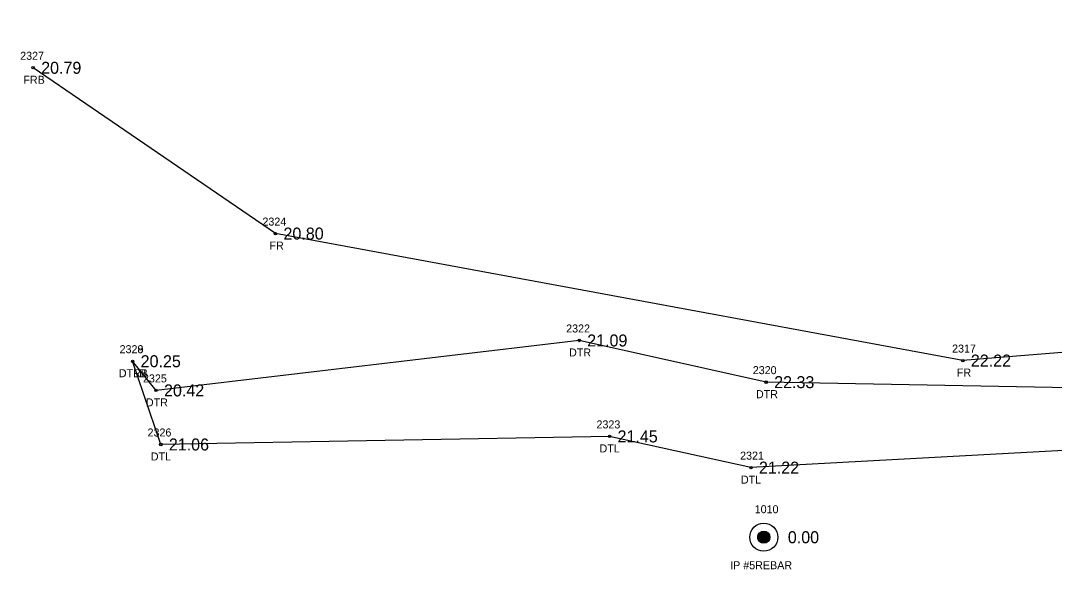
# Model space of a CAD drawing. Extents: x 2654414 to 2656963, y 761776 to 764965.
# Drawn here: x 2655219.9 to 2655349, y 762027.7 to 762096.2 of the extents above; entities that cross this region are included whole.
import ezdxf

# ---------------------------------------------------------------- set-up
doc = ezdxf.new("R2010")
doc.units = 0
for name, color, linetype in [('RD_EX_DV_Prop_txCode', 7, 'Continuous'), ('RD_EX_DV_PropPin', 7, 'Continuous'), ('RD_EX_Fence_Other', 7, 'Continuous'), ('RD_EX_Fence_Other_txCode', 7, 'Continuous'), ('RD_EX_H2O', 7, 'Continuous'), ('RD_EX_H2O_txCode', 7, 'Continuous'), ('RD_EX_TX_DV_Prop_ELEV', 7, 'Continuous'), ('RD_EX_TX_Fence_Other_ELEV', 7, 'Continuous'), ('RD_EX_TX_H2O_ELEV', 7, 'Continuous'), ('RD_SMD_Locator', 7, 'Continuous')]:
    doc.layers.add(name, color=color, linetype=linetype)

msp = doc.modelspace()

# ---------------------------------------------------------------- linework, layer by layer
at = {"layer": 'RD_EX_DV_PropPin'}
for p, q in [((2655312.11, 762031.2), (2655312.11, 762032.15)), ((2655312.15, 762031.16), (2655312.15, 762032.19)), ((2655312.18, 762031.12), (2655312.18, 762032.22)), ((2655312.22, 762031.09), (2655312.22, 762032.25)), ((2655312.25, 762031.06), (2655312.25, 762032.28)), ((2655312.29, 762031.04), (2655312.29, 762032.31)), ((2655312.32, 762031.01), (2655312.32, 762032.33)), ((2655312.36, 762031), (2655312.36, 762032.35)), ((2655312.39, 762030.98), (2655312.39, 762032.36)), ((2655312.43, 762030.96), (2655312.43, 762032.38)), ((2655312.46, 762030.95), (2655312.46, 762032.39)), ((2655312.5, 762030.94), (2655312.5, 762032.4)), ((2655312.53, 762030.93), (2655312.53, 762032.41)), ((2655312.57, 762030.92), (2655312.57, 762032.42)), ((2655312.6, 762030.92), (2655312.6, 762032.42)), ((2655312.64, 762030.91), (2655312.64, 762032.43)), ((2655312.67, 762030.91), (2655312.67, 762032.43)), ((2655312.71, 762030.91), (2655312.71, 762032.43)), ((2655312.74, 762030.91), (2655312.74, 762032.43)), ((2655312.78, 762030.91), (2655312.78, 762032.43)), ((2655312.81, 762030.92), (2655312.81, 762032.42)), ((2655312.85, 762030.92), (2655312.85, 762032.42)), ((2655312.88, 762030.93), (2655312.88, 762032.41)), ((2655312.92, 762030.94), (2655312.92, 762032.4)), ((2655312.95, 762030.95), (2655312.95, 762032.39)), ((2655312.99, 762030.96), (2655312.99, 762032.38)), ((2655313.02, 762030.98), (2655313.02, 762032.36)), ((2655313.06, 762031), (2655313.06, 762032.35)), ((2655313.09, 762031.01), (2655313.09, 762032.33)), ((2655313.13, 762031.04), (2655313.13, 762032.31)), ((2655313.16, 762031.06), (2655313.16, 762032.28)), ((2655313.2, 762031.09), (2655313.2, 762032.25)), ((2655313.23, 762031.12), (2655313.23, 762032.22)), ((2655313.27, 762031.16), (2655313.27, 762032.19)), ((2655313.3, 762031.2), (2655313.3, 762032.15)), ((2655311.97, 762031.48), (2655311.97, 762031.87)), ((2655312.01, 762031.37), (2655312.01, 762031.97)), ((2655312.04, 762031.3), (2655312.04, 762032.04)), ((2655312.08, 762031.24), (2655312.08, 762032.1)), ((2655313.34, 762031.24), (2655313.34, 762032.1)), ((2655313.37, 762031.3), (2655313.37, 762032.04)), ((2655313.41, 762031.37), (2655313.41, 762031.97)), ((2655313.44, 762031.48), (2655313.44, 762031.87))]:
    msp.add_line(p, q, dxfattribs=at)
for radius in [1.75, 0.761]:
    msp.add_circle((2655312.71, 762031.67), radius, dxfattribs=at)
at = {"layer": 'RD_EX_Fence_Other'}
msp.add_lwpolyline([(2655431.78, 762175.86), (2655417.3, 762172.91), (2655393.28, 762058.24), (2655393.28, 762058.24), (2655337.57, 762053.75), (2655251.71, 762069.62), (2655221.44, 762090.34)], dxfattribs=at)
at = {"layer": 'RD_EX_H2O'}
for points in [[(2655388.95, 762049.63), (2655313, 762051.05), (2655289.65, 762056.26), (2655236.79, 762050.02), (2655233.87, 762053.67)], [(2655386.96, 762044.53), (2655311.1, 762040.37), (2655293.44, 762044.27), (2655237.39, 762043.26), (2655233.87, 762053.67)]]:
    msp.add_lwpolyline(points, dxfattribs=at)
at = {"layer": 'RD_SMD_Locator'}
for centre in [(2655221.44, 762090.34), (2655251.71, 762069.62), (2655289.65, 762056.26), (2655233.87, 762053.67), (2655233.87, 762053.67), (2655337.57, 762053.75), (2655313, 762051.05), (2655236.79, 762050.02), (2655293.44, 762044.27), (2655237.39, 762043.26), (2655311.1, 762040.37), (2655312.71, 762031.67)]:
    msp.add_circle(centre, 0.15, dxfattribs=at)

# ---------------------------------------------------------------- texts
at = {"layer": 'RD_EX_DV_Prop_txCode'}
for s, p in [('1010', (2655311.57, 762034.67)), ('IP #5REBAR', (2655308.51, 762027.67))]:
    msp.add_text(s, height=1, dxfattribs=at).set_placement(p)
at = {"layer": 'RD_EX_Fence_Other_txCode'}
for s, p in [('2327', (2655219.82, 762091.34)), ('FRB', (2655220.22, 762088.34)), ('2324', (2655250.08, 762070.62)), ('FR', (2655250.96, 762067.62)), ('2317', (2655336.23, 762054.75)), ('FR', (2655336.82, 762051.75))]:
    msp.add_text(s, height=1, dxfattribs=at).set_placement(p)
at = {"layer": 'RD_EX_H2O_txCode'}
for s, p in [('2322', (2655288.02, 762057.26)), ('2328', (2655232.24, 762054.67)), ('2329', (2655232.24, 762054.67)), ('DTR', (2655288.38, 762054.26)), ('2320', (2655311.33, 762052.05)), ('DTRB', (2655232.13, 762051.67)), ('DTLB', (2655232.15, 762051.67)), ('2325', (2655235.16, 762051.02)), ('DTR', (2655235.52, 762048.02)), ('DTR', (2655311.73, 762049.05)), ('2326', (2655235.73, 762044.26)), ('2323', (2655291.81, 762045.27)), ('DTL', (2655292.19, 762042.27)), ('DTL', (2655236.14, 762041.26)), ('2321', (2655309.75, 762041.37)), ('DTL', (2655309.85, 762038.37))]:
    msp.add_text(s, height=1, dxfattribs=at).set_placement(p)
at = {"layer": 'RD_EX_TX_DV_Prop_ELEV'}
msp.add_text('0.00', height=1.5, dxfattribs=at).set_placement((2655315.71, 762030.92))
at = {"layer": 'RD_EX_TX_Fence_Other_ELEV'}
for s, p in [('20.79', (2655222.44, 762089.59)), ('20.80', (2655252.71, 762068.87)), ('22.22', (2655338.57, 762053))]:
    msp.add_text(s, height=1.5, dxfattribs=at).set_placement(p)
at = {"layer": 'RD_EX_TX_H2O_ELEV'}
for s, p in [('21.09', (2655290.65, 762055.51)), ('20.25', (2655234.87, 762052.92)), ('20.25', (2655234.87, 762052.92)), ('22.33', (2655314, 762050.3)), ('20.42', (2655237.79, 762049.27)), ('21.06', (2655238.39, 762042.51)), ('21.45', (2655294.44, 762043.52)), ('21.22', (2655312.1, 762039.62))]:
    msp.add_text(s, height=1.5, dxfattribs=at).set_placement(p)

doc.saveas('drawing.dxf')
